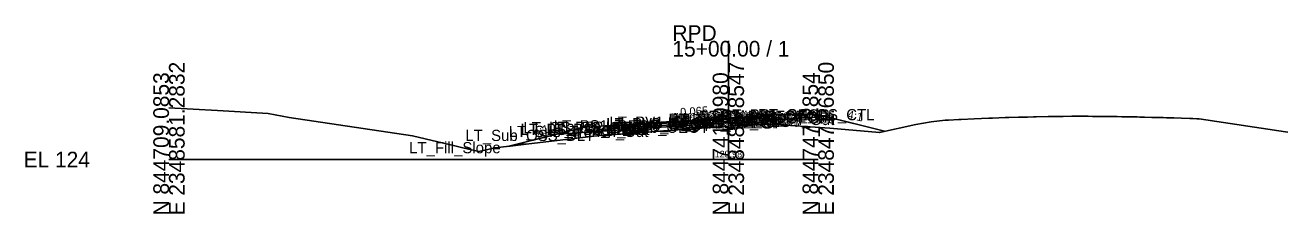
# Model space of a CAD drawing. Extents: x -26 to 2348536, y -510 to 844755.
# Drawn here: x -25.7 to 200, y -9.7 to 24 of the extents above; entities that cross this region are included whole.
import ezdxf

# ---------------------------------------------------------------- set-up
doc = ezdxf.new("R2010")
doc.units = 0
for name, color, linetype in [('Default', 7, 'Continuous'), ('Exist Cross Section Cell', 7, 'Continuous'), ('Exist XS Center Line Elevation Label', 7, 'Continuous'), ('Exist XS Ground Line', 7, 'Continuous'), ('Prop CMT Pvmt Course 1', 7, 'Continuous'), ('Prop CMT Pvmt Course 2', 7, 'Continuous'), ('Prop CMT Pvmt Course 3', 7, 'Continuous'), ('Prop CMT Pvmt Surface', 7, 'Continuous'), ('Prop CMT Pvmt Surface Shoulder', 7, 'Continuous'), ('Prop CMT Shld Paved Course 1', 7, 'Continuous'), ('Prop CMT Shld Paved Course 2', 7, 'Continuous'), ('Prop CMT Shld Paved Course 3', 7, 'Continuous'), ('Prop CMT Slope Grass', 7, 'Continuous'), ('Prop CMT Subgrade Earthwork', 7, 'Continuous'), ('Prop XS Earthwork Shape', 7, 'Continuous'), ('Prop XS SE Text', 7, 'Continuous'), ('Prop XS Side Slope Text', 7, 'Continuous'), ('Scratch_Level_0', 7, 'Continuous')]:
    doc.layers.add(name, color=color, linetype=linetype)

msp = doc.modelspace()

# ---------------------------------------------------------------- linework, layer by layer
at = {"layer": 'Exist Cross Section Cell'}
for p, q in [((100, 0), (100, 21.22)), ((0, 0), (100, 0)), ((100, 0), (116.06, 0))]:
    msp.add_line(p, q, dxfattribs=at)
at = {"layer": 'Exist XS Ground Line'}
msp.add_lwpolyline([(0, 9.26), (8.67, 8.79), (17.72, 8.21), (21.49, 7.51), (43.52, 4.22), (51.36, 2.38), (52.55, 2.1), (55.4, 1.46), (58.3, 2.1), (63.84, 2.74), (76.99, 4.3), (77.72, 4.34), (79.82, 4.51), (80.48, 4.53), (80.79, 4.56), (83.01, 4.71), (84.22, 4.81), (85.66, 4.92), (86.36, 4.97), (88.38, 5.12), (90.32, 5.25), (90.97, 5.3), (92.33, 5.4), (93.58, 5.49), (94.24, 5.58), (96.21, 5.7), (98.13, 5.85), (98.87, 5.9), (100.06, 5.98), (101.57, 6.09), (102.13, 6.12), (103.44, 6.22), (104.11, 6.27), (105.92, 6.32), (106.76, 6.32), (107.54, 6.31), (108.46, 6.29), (118.13, 5.59), (127.03, 4.85), (133.5, 6.26), (136.24, 6.74), (138.78, 7.04), (139.37, 7.05), (141.22, 7.16), (141.63, 7.18), (143.95, 7.29), (145.28, 7.35), (146.55, 7.4), (147.23, 7.43), (149.5, 7.53), (150.15, 7.54), (151.88, 7.57), (153.46, 7.61), (154.53, 7.64), (155.05, 7.65), (157.16, 7.68), (159.05, 7.7), (159.84, 7.71), (161.42, 7.74), (161.75, 7.75), (162.29, 7.75), (164.31, 7.74), (165.09, 7.73), (165.5, 7.73), (167.72, 7.72), (169.52, 7.68), (170.35, 7.67), (170.75, 7.66), (172.07, 7.64), (173.06, 7.62), (173.57, 7.61), (174.4, 7.58), (175.68, 7.55), (177.7, 7.5), (178.35, 7.48), (178.66, 7.47), (179.66, 7.44), (181, 7.4), (182.48, 7.34), (183.03, 7.33), (183.77, 7.29), (184.14, 7.28), (199.59, 4.97), (200, 4.9)], dxfattribs=at)
at = {"layer": 'Prop CMT Pvmt Course 1'}
for p, q in [((100, 7.47), (88, 6.69)), ((88, 6.44), (100, 7.22)), ((100, 7.47), (104, 7.73)), ((104, 7.48), (100, 7.22)), ((100, 7.22), (100, 7.47)), ((100, 7.22), (100, 7.47)), ((100, 7.22), (100, 7.35)), ((100, 7.35), (100, 7.35)), ((100, 7.35), (100, 7.22)), ((100, 7.22), (100, 7.35)), ((100, 7.35), (100, 7.35)), ((100, 7.35), (100, 7.22)), ((100, 7.22), (100, 7.22)), ((100, 7.22), (100, 7.22)), ((104, 7.73), (104, 7.48)), ((88, 6.69), (88, 6.44))]:
    msp.add_line(p, q, dxfattribs=at)
at = {"layer": 'Prop CMT Pvmt Course 2'}
for p, q in [((100, 7.22), (88, 6.44)), ((88, 6.11), (100, 6.89)), ((100, 7.22), (104, 7.48)), ((100, 6.89), (100, 7.22)), ((100, 6.89), (100, 7.22)), ((104, 7.15), (100, 6.89)), ((104, 7.48), (104, 7.15)), ((88, 6.44), (88, 6.11))]:
    msp.add_line(p, q, dxfattribs=at)
at = {"layer": 'Prop CMT Pvmt Course 3'}
for p, q in [((100, 6.89), (88, 6.11)), ((100, 6.89), (104, 7.15)), ((100, 6.56), (100, 6.89)), ((100, 6.56), (100, 6.89)), ((104, 6.82), (100, 6.56)), ((104, 7.15), (104, 6.82)), ((88, 5.78), (100, 6.56)), ((88, 6.11), (88, 5.78))]:
    msp.add_line(p, q, dxfattribs=at)
at = {"layer": 'Prop CMT Pvmt Surface'}
for q in [(88, 6.69), (104, 7.73)]:
    msp.add_line((100, 7.47), q, dxfattribs=at)
at = {"layer": 'Prop CMT Pvmt Surface Shoulder'}
for p, q in [((104, 7.73), (108, 7.99)), ((88, 6.69), (78, 6.04))]:
    msp.add_line(p, q, dxfattribs=at)
at = {"layer": 'Prop CMT Shld Paved Course 1'}
for p, q in [((104, 7.73), (108, 7.99)), ((108.23, 7.76), (104, 7.48)), ((104, 7.48), (104, 7.73)), ((108, 7.99), (108.23, 7.76)), ((77.73, 5.78), (88, 6.44)), ((78, 6.04), (77.73, 5.78)), ((88, 6.69), (78, 6.04)), ((88, 6.44), (88, 6.69))]:
    msp.add_line(p, q, dxfattribs=at)
at = {"layer": 'Prop CMT Shld Paved Course 2'}
for p, q in [((104, 7.48), (108.23, 7.76)), ((104, 7.15), (104, 7.48)), ((108.55, 7.45), (104, 7.15)), ((108.23, 7.76), (108.55, 7.45)), ((77.38, 5.42), (88, 6.11)), ((77.73, 5.78), (77.38, 5.42)), ((88, 6.44), (77.73, 5.78)), ((88, 6.11), (88, 6.44))]:
    msp.add_line(p, q, dxfattribs=at)
at = {"layer": 'Prop CMT Shld Paved Course 3'}
for p, q in [((104, 7.15), (108.55, 7.45)), ((109.36, 7.17), (104, 6.82)), ((104, 6.82), (104, 7.15)), ((108.55, 7.45), (109.05, 7.48)), ((109.05, 7.48), (109.36, 7.17)), ((76.52, 5.03), (88, 5.78)), ((76.88, 5.39), (76.52, 5.03)), ((77.38, 5.42), (76.88, 5.39)), ((88, 6.11), (77.38, 5.42)), ((88, 5.78), (88, 6.11))]:
    msp.add_line(p, q, dxfattribs=at)
at = {"layer": 'Prop CMT Slope Grass'}
for p, q in [((108, 7.99), (116, 8.03)), ((116, 8.03), (127.93, 5.05)), ((74, 5.72), (60.53, 2.36)), ((78, 6.04), (74, 5.72))]:
    msp.add_line(p, q, dxfattribs=at)
at = {"layer": 'Prop CMT Subgrade Earthwork'}
for p, q in [((100, 6.56), (104, 6.82)), ((104, 6.82), (117.39, 7.69)), ((76.52, 5.03), (69.37, 4.57)), ((88, 5.78), (76.52, 5.03)), ((100, 6.56), (88, 5.78))]:
    msp.add_line(p, q, dxfattribs=at)
at = {"layer": 'Prop XS Earthwork Shape'}
msp.add_lwpolyline([(76.52, 5.03), (69.37, 4.57), (60.53, 2.36), (63.84, 2.74), (76.99, 4.3), (77.72, 4.34), (79.82, 4.51), (80.48, 4.53), (80.79, 4.56), (83.01, 4.71), (84.22, 4.81), (85.66, 4.92), (86.36, 4.97), (88.38, 5.12), (90.32, 5.25), (90.97, 5.3), (92.33, 5.4), (93.58, 5.49), (94.24, 5.58), (96.21, 5.7), (98.13, 5.85), (98.87, 5.9), (100.06, 5.98), (101.57, 6.09), (102.13, 6.12), (103.44, 6.22), (104.11, 6.27), (105.92, 6.32), (106.76, 6.32), (107.54, 6.31), (108.46, 6.29), (118.13, 5.59), (127.03, 4.85), (127.93, 5.05), (117.39, 7.69), (104, 6.82), (100, 6.56), (88, 5.78)], close=True, dxfattribs=at)

# ---------------------------------------------------------------- texts
at = {"layer": 'Default'}
msp.add_text('-', height=0.0001, dxfattribs=at).set_placement((0, 0))
at = {"layer": 'Exist Cross Section Cell'}
for s, p in [('RPD', (90, 21.22)), ('15+00.00 / 1', (90, 18.42)), ('EL 124', (-26, -1.4))]:
    msp.add_text(s, height=2.8, dxfattribs=at).set_placement(p)
for s, p in [('E 2348581.2832', (2.8, -10)), ('E 2348486.8547', (102.8, -10)), ('E 2348471.6850', (118.86, -10)), ('N 844709.0853', (0, -10)), ('N 844741.9980', (100, -10)), ('N 844747.2854', (116.06, -10))]:
    msp.add_text(s, height=2.8, rotation=90, dxfattribs=at).set_placement(p)
at = {"layer": 'Exist XS Center Line Elevation Label'}
msp.add_text('129.98', height=1.2, dxfattribs=at).set_placement((97.55, 0.38))
at = {"layer": 'Prop XS SE Text'}
msp.add_text('0.065', height=1.5, rotation=3.719, dxfattribs=at).set_placement((91.42, 7.71))
at = {"layer": 'Prop XS Side Slope Text'}
for rotation, p in [(348.0249, (121.17, 7.38)), (14.0362, (65.32, 4.15))]:
    msp.add_text('4:1', height=1.5, rotation=rotation, dxfattribs=at).set_placement(p)
at = {"layer": 'Scratch_Level_0'}
for s, p in [('RT_GS_OS_CTL', (105.32, 7.03)), ('LT_PS2_OEOP', (67.97, 4.78)), ('LT_PS1_OEOP', (68.8, 5.04)), ('LT_Sub_OEOT', (78.08, 4.78)), ('LT_PV2_OEOT', (78.17, 5.44)), ('LT_PV3_OEOT', (78.17, 5.11)), ('LT_PV1_OEOT', (78.74, 5.69)), ('RT_Sub_OEEOP', (89.17, 5.56)), ('LT_Sub_OEEOP', (89.21, 5.56)), ('RT_PV2_OEEOP', (89.26, 6.22)), ('RT_PV3_OEEOP', (89.26, 5.89)), ('LT_PV2_OEEOP', (89.31, 6.22)), ('LT_PV3_OEEOP', (89.31, 5.89)), ('RT_PV1_OEEOP', (89.83, 6.35)), ('LT_PV1_OEEOP', (89.87, 6.35)), ('RT_PV2_IEEOP', (89.91, 6.22)), ('LT_PV2_IEEOP', (89.95, 6.22)), ('RT_PV1_IEEOP', (90.47, 6.35)), ('LT_PV1_IEEOP', (90.52, 6.35)), ('RT_Sub_Trench_Out', (93.52, 6.17)), ('PV2_PGL', (93.91, 6.22)), ('RT_Sub_OEOT', (94.03, 5.82)), ('RT_PV2_OEOT', (94.13, 6.48)), ('RT_PV3_OEOT', (94.13, 6.15)), ('PV1_PGL', (94.47, 6.47)), ('RT_PV1_OEOT', (94.69, 6.73)), ('RT_PS3_Shelf_Out', (94.98, 6.48)), ('RT_PS2_OEOP', (98.42, 6.76)), ('RT_PS3_OEOP', (98.74, 6.45)), ('RT_PS1_OEOP', (98.76, 6.99)), ('LT_Sub_OSS_DLT', (52.98, 3.32)), ('LT_Sub_Trench_Out', (60.72, 4.03)), ('LT_PS3_Shelf_Out', (62.86, 4.39)), ('LT_GS_OS_CTL', (63.37, 4.72)), ('LT_PS3_OEOP', (67.61, 4.42)), ('LT_Fill_Slope', (42.94, 1.13))]:
    msp.add_text(s, height=2, dxfattribs=at).set_placement(p)

doc.saveas('drawing.dxf')
